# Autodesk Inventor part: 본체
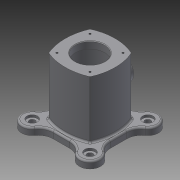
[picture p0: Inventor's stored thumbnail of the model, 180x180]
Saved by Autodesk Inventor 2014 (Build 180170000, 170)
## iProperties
Created: 2016-05
Part Number: 본체
Material: Generic
Document SubType Name: Modeling
Designer: user
Density: 1 g/cm^3
Appearance: Default
Author: user
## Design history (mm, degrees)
sketch "Sketch1"
  geometry: L1 (0, 0)-(108.894, 0); L2 (0, 0)-(113.137, 0); L3 (0, 0)-(137.179, 0); L4 (0, 0)-(113.137, 0); L5 (49, 14.162)-(49, -14.162); L6 (14.162, -49)-(-14.162, -49); L7 (-49, -14.162)-(-49, 14.162); L8 (14.162, 49)-(-14.162, 49); A1 r 18 centre (49.497, 49.497) between (59.754, 34.706) and (34.706, 59.754); A2 r 18 centre (-49.497, 49.497) between (-34.706, 59.754) and (-59.754, 34.706); A3 r 18 centre (49.497, -49.497) between (34.706, -59.754) and (59.754, -34.706); A4 r 18 centre (-49.497, -49.497) between (-59.754, -34.706) and (-34.706, -59.754); A5 r 25 centre (-74, 14.162) between (-49, 14.162) and (-59.754, 34.706); A6 r 25 centre (-74, -14.162) between (-59.754, -34.706) and (-49, -14.162); A7 r 25 centre (-14.162, -74) between (-14.162, -49) and (-34.706, -59.754); A8 r 25 centre (14.162, -74) between (34.706, -59.754) and (14.162, -49); A9 r 25 centre (74, -14.162) between (49, -14.162) and (59.754, -34.706); A10 r 25 centre (74, 14.162) between (59.754, 34.706) and (49, 14.162); A11 r 25 centre (-14.162, 74) between (-34.706, 59.754) and (-14.162, 49); A12 r 25 centre (14.162, 74) between (14.162, 49) and (34.706, 59.754); 9 further points
  constraints: 30 point on circle, 16 end point, 12 centre point, 12 tangent, 6 point on line, 5 equal radius, 4 horizontal, 1 horizontal alignment, 1 midpoint, 1 parallel, 1 vertical alignment
  dimensions: "d3" = 36 diameter of A1; "d9" = 36 diameter of A2; "d10" = 36 diameter of A3; "d11" = 36 diameter of A4; "d14" = 25 radius of A5
extrude "Extrusion1" new body sketch "Sketch1" distance "d15" = 12; taper "d16" = 0 deg
sketch "Sketch2"
  geometry: L1 (0, 0)-(50, 0); L2 (0, 0)-(50, 0); L3 (0, 0)-(50, 0); L4 (0, 0)-(50, 0); A1 r 85.579 centre (0, -42.579) between (35.355, 35.355) and (-35.355, 35.355); A2 r 85.579 centre (-42.579, 0) between (35.355, -35.355) and (35.355, 35.355); A3 r 90.136 centre (47.557, 0) between (-35.355, 35.355) and (-35.355, -35.355); A4 r 90.136 centre (0, 47.557) between (-35.355, -35.355) and (35.355, -35.355); 2 further points
  constraints: 11 point on circle, 8 end point, 4 centre point, 4 horizontal, 1 horizontal alignment, 1 vertical alignment
  dimensions: "d19" = 50 distance of L1.start A1.start; "d21" = 50 distance of L1.start A3.end; "d23" = 50 distance of L1.start A2.start; "d25" = 50 distance of L1.start A1.end
extrude "Extrusion2" join sketch "Sketch2" distance "d27" = 98; taper "d28" = 0 deg
workplane "Work Plane1"
sketch "Sketch3"
  geometry: L1 (67.497, 12)-(34.706, 12) reference; C1 r 20 at (0, 61); 2 further points
  constraints: 1 centre point
  dimensions: "d30" = 40 diameter of C1; "d31" = 49 distance from line of L1 C1.centre
extrude "Extrusion3" join sketch "Sketch3" distance "d32" = 40 (= d30); taper "d33" = 10 deg
sketch "Sketch4"
  geometry: C1 r 25 at (0, 0); 1 further point
  constraints: 1 centre point, 1 coincident
  dimensions: "d34" = 50 diameter of C1
extrude "Extrusion4" cut sketch "Sketch4" distance "d35" = 12; taper "d36" = 0 deg
sketch "Sketch5"
  geometry: C1 r 25 at (0, 0) reference; C2 r 35 at (0, 0)
  constraints: 1 centre point, 1 coincident
  dimensions: "d37" = 70 diameter of C2
extrude "Extrusion5" cut sketch "Sketch5" distance "d38" = 86; taper "d39" = 0 deg
sketch "Sketch6"
  geometry: C1 r 25 at (0, 0); 1 further point
  constraints: 1 centre point, 1 coincident
  dimensions: "d40" = 50 diameter of C1
extrude "Extrusion6" cut sketch "Sketch6" distance "d41" = 12; taper "d42" = 0 deg
sketch "Sketch7"
  geometry: C1 r 20 at (0, 0) reference; C2 r 15 at (0, 0); 1 further point
  constraints: 1 centre point, 1 coincident
  dimensions: "d43" = 30 diameter of C2
extrude "Extrusion7" cut sketch "Sketch7" distance "d44" = 8; taper "d45" = 0 deg
sketch "Sketch8"
  geometry: C1 r 15 at (0, 0) reference; C2 r 12.5 at (0, 0); 1 further point
  constraints: 1 centre point, 1 coincident
  dimensions: "d46" = 25 diameter of C2
extrude "Extrusion8" cut sketch "Sketch8" stored distance "d47" = 8; taper "d48" = 0 deg
sketch "Sketch10"
  geometry: L1 (0, 0)-(69.296, 0); C1 r 25 at (0, 0) reference; 1 further point
  constraints: 2 end point, 1 coincident, 1 horizontal
hole "Hole2" sketch "Sketch10" at (28.284, 28.284) diameter "d61" = 3.242; stored, may be unused: countersink angle "d65" = 90 deg, drill point angle "d67" = 118 deg; dims "d62" = 7, "d63" = 18, "d64" = 4, "d66" = 10
pattern_circular "Circular Pattern2" dims angle "d69" = 360 deg
sketch "Sketch11"
  geometry: L1 (0, 0)-(114.551, 0); C1 r 25 at (0, 0) reference; 1 further point
  constraints: 2 end point, 1 coincident, 1 horizontal
hole "Hole3" sketch "Sketch11" at (28.284, 28.284) diameter "d73" = 3.242; stored, may be unused: countersink angle "d77" = 90 deg, drill point angle "d79" = 118 deg; dims "d74" = 7, "d75" = 18, "d76" = 4, "d78" = 10
pattern_circular "Circular Pattern3" dims angle "d81" = 360 deg
chamfer "Chamfer1" distance "d83" = 1; stored, may be unused: second distance "d84" = 2, angle "d85" = 45 deg
fillet "Fillet1" dims "d86" = 3
chamfer "Chamfer2" distance "d87" = 1; stored, may be unused: second distance "d88" = 2, angle "d89" = 45 deg
fillet "Fillet2" dims "d90" = 3
fillet "Fillet3" dims "d91" = 3
fillet "Fillet4" dims "d92" = 3
fillet "Fillet5" dims "d93" = 3
sketch "Sketch12"
  geometry: L1 (46, 14.162)-(46, 0) reference; L2 (0, 46)-(14.162, 46) reference; C1 r 9 at (-49.497, 49.497); A1 r 15 centre (-49.497, 49.497) between (-37.171, 58.045) and (-58.045, 37.171) reference; A2 r 28 centre (74, 14.162) between (58.045, 37.171) and (46, 14.162) reference; A3 r 15 centre (49.497, 49.497) between (58.045, 37.171) and (37.171, 58.045) reference; A4 r 28 centre (14.162, 74) between (14.162, 46) and (37.171, 58.045) reference; A5 r 88.579 centre (0, -42.579) between (35.487, 38.581) and (0, 46) reference; A6 r 6 centre (33.083, 33.083) between (38.581, 35.487) and (35.487, 38.581) reference; A7 r 88.579 centre (-42.579, 0) between (46, 0) and (38.581, 35.487) reference; 1 further point
  constraints: 1 centre point, 1 coincident
  dimensions: "d94" = 18 diameter of C1
extrude "Extrusion9" cut sketch "Sketch12" distance "d95" = 4; taper "d96" = 0 deg
sketch "Sketch13"
  geometry: C1 r 9 at (0, 0) reference; C2 r 5 at (0, 0); 1 further point
  constraints: 1 centre point, 1 coincident
  dimensions: "d97" = 10 diameter of C2
extrude "Extrusion10" cut sketch "Sketch13" distance "d98" = 8; taper "d99" = 0 deg
pattern_circular "Circular Pattern4" dims angle "d101" = 360 deg
workplane "Work Plane2"
sketch "Sketch15"
  geometry: L1 (-23.235, 81.739)-(-23.235, 40.261); L2 (-23.235, 40.261)-(-34.765, 40.261); L3 (-34.765, 40.261)-(-34.765, 81.739); L4 (-34.765, 81.739)-(-23.235, 81.739); L5 (34.248, 110)-(-34.285, 110) reference; 4 further points
  constraints: 2 midpoint, 1 horizontal alignment, 1 vertical alignment, 2 other
  dimensions: "d108" = 29 horizontal distance of point (0, 0) point (-29, 61); "d109" = 49 distance from line of point (-29, 61) L5
emboss "Emboss2" sketch "Sketch15" dims "d3" = 36, "d9" = 36, "d10" = 36, "d11" = 36, "d14" = 25, "d110" = 0.5, "d111" = 0
body "Solid1"
node "Projected Loop1"
other parameters: "d29" = 55, "d103" = 43
